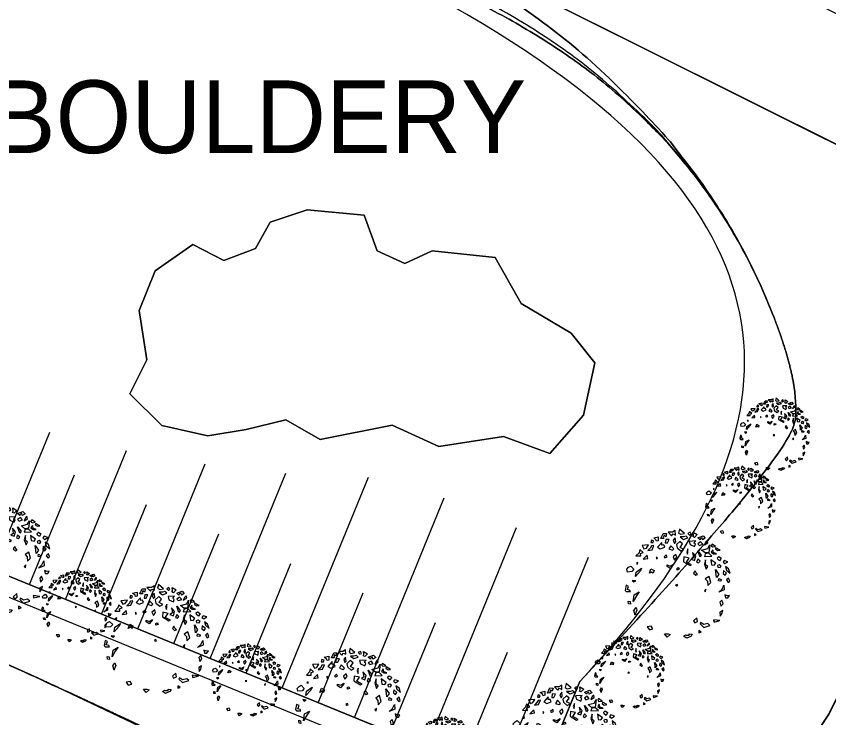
# Model space of a CAD drawing. Extents: x -504998 to -504814, y -1117353 to -1117234.
# Drawn here: x -504898.37 to -504887.95, y -1117325.65 to -1117316.66 of the extents above; entities that cross this region are included whole.
import ezdxf

# ---------------------------------------------------------------- set-up
doc = ezdxf.new("R2010")
doc.units = 0
for name, color, linetype in [('01_OPLOCENI', 7, 'Continuous'), ('01_ST tenká', 7, 'Continuous'), ('03_POPIS', 7, 'Continuous'), ('05_ZARIZ_PREDMETY', 7, 'Continuous'), ('10_ZIVE_PLOTY_KVETOUCI', 7, 'Continuous'), ('_01_CYKLOSTEZKA', 7, 'Continuous'), ('_01_pl', 7, 'Continuous'), ('_01_reka', 7, 'Continuous'), ('_01_ST tenká', 7, 'Continuous'), ('_01_svah', 7, 'Continuous'), ('_02_pl_ cesta', 7, 'Continuous'), ('Default', 7, 'Continuous'), ('res_uzemi', 7, 'Continuous')]:
    doc.layers.add(name, color=color, linetype=linetype)

# ---------------------------------------------------------------- blocks, each defined once
blk = doc.blocks.new('Deciduous Tree 1 PV_1')
at = {"layer": 'Default'}
for points in [[(-0.2248, 0.4729), (-0.2292, 0.4866), (-0.2556, 0.5084), (-0.207, 0.5208), (-0.2071, 0.4786)], [(-0.1783, 0.5014), (-0.1534, 0.5564), (-0.1189, 0.5548), (-0.128, 0.5216), (-0.1454, 0.5343), (-0.1535, 0.5142), (-0.1468, 0.5028)], [(-0.1029, 0.57), (-0.0664, 0.5317), (-0.0498, 0.553), (-0.0232, 0.5402), (-0.0265, 0.587), (-0.0564, 0.57)], [(0.021, 0.6025), (0.01, 0.5615), (0.0332, 0.5488), (0.073, 0.5573)], [(0.0265, 0.519), (0.063, 0.4935), (0.1095, 0.5105), (0.0896, 0.5275), (0.063, 0.519)], [(0.1327, 0.57), (0.1095, 0.5573), (0.1261, 0.5402), (0.1427, 0.5488)], [(0.1626, 0.5232), (0.1692, 0.536), (0.1659, 0.57), (0.209, 0.5445), (0.1792, 0.5147)], [(0.2157, 0.5105), (0.2721, 0.5317), (0.2953, 0.5062), (0.2655, 0.4892), (0.2621, 0.5105), (0.2422, 0.502), (0.2389, 0.4892)], [(-0.279, 0.4849), (-0.2864, 0.4595), (-0.2627, 0.4592), (-0.2569, 0.4769)], [(-0.1706, 0.461), (-0.2169, 0.4087), (-0.1858, 0.3917), (-0.1379, 0.4095), (-0.1489, 0.4345), (-0.1697, 0.4318)], [(-0.1271, 0.4925), (-0.1331, 0.4563), (-0.1094, 0.456), (-0.0926, 0.4909)], [(-0.0265, 0.5105), (-0.0465, 0.4849), (-0.0332, 0.4509), (-0.0199, 0.4679)], [(0.0232, 0.4722), (-0.0133, 0.4382), (-0.0066, 0.4041), (0.0332, 0.3701), (0.0664, 0.3871), (0.0265, 0.4084), (0.0531, 0.4467)], [(0.1925, 0.4764), (0.1228, 0.4722), (0.1327, 0.4382), (0.1792, 0.4169), (0.1891, 0.4424), (0.1725, 0.4552)], [(0.2455, 0.4679), (0.2157, 0.4467), (0.2323, 0.4296), (0.2688, 0.4424)], [(0.3152, 0.4807), (0.2986, 0.4637), (0.2854, 0.4339), (0.3219, 0.4552)], [(0.3683, 0.4424), (0.3584, 0.4254), (0.3716, 0.4126), (0.4048, 0.4169)], [(-0.4456, 0.3183), (-0.3927, 0.3171), (-0.396, 0.3438), (-0.3682, 0.3536), (-0.4037, 0.3843), (-0.4128, 0.3512)], [(-0.381, 0.4289), (-0.3598, 0.3921), (-0.3344, 0.3995), (-0.3122, 0.4336)], [(-0.318, 0.3737), (-0.2742, 0.3815), (-0.2533, 0.4264), (-0.2794, 0.4243), (-0.2922, 0.3995)], [(-0.073, 0.4254), (-0.0929, 0.3914), (-0.0564, 0.3786), (-0.0398, 0.3914)], [(0.1095, 0.3914), (0.0962, 0.3616), (0.1062, 0.3361), (0.1095, 0.3616)], [(0.1593, 0.3531), (0.1692, 0.2978), (0.1427, 0.2808), (0.1792, 0.268), (0.1925, 0.3148)], [(0.2389, 0.302), (0.2157, 0.3701), (0.2522, 0.3233)], [(0.2555, 0.3786), (0.3219, 0.3956), (0.3418, 0.4339), (0.3318, 0.3531), (0.292, 0.3488)], [(0.375, 0.3829), (0.3584, 0.3573), (0.3816, 0.3403), (0.4148, 0.3403), (0.3816, 0.3531)], [(0.4081, 0.4041), (0.4048, 0.3914), (0.428, 0.3743), (0.4546, 0.3786)], [(-0.3252, 0.3233), (-0.3683, 0.2808), (-0.3185, 0.2893)], [(-0.2256, 0.3063), (-0.2256, 0.285), (-0.2157, 0.2935)], [(-0.1228, 0.3276), (-0.146, 0.3063), (-0.136, 0.2978), (-0.1128, 0.3063)], [(-0.0199, 0.3318), (-0.0498, 0.3063), (-0.0332, 0.2723), (-0.01, 0.302)], [(0.0664, 0.3063), (0.063, 0.2552), (0.1327, 0.2127), (0.1493, 0.2212), (0.0929, 0.251), (0.1228, 0.2935)], [(0.2157, 0.2808), (0.2024, 0.251), (0.2223, 0.2425), (0.2389, 0.2595)], [(0.2953, 0.3403), (0.2854, 0.3105), (0.365, 0.3148), (0.3318, 0.3446)], [(0.2986, 0.2765), (0.2854, 0.2297), (0.3053, 0.1744), (0.3219, 0.2042), (0.2986, 0.2212)], [(0.355, 0.2765), (0.3617, 0.2212), (0.3915, 0.2169), (0.4081, 0.2382)], [(0.448, 0.2637), (0.428, 0.2808), (0.4247, 0.2978), (0.438, 0.3105), (0.4645, 0.2935)], [(0.4977, 0.268), (0.4845, 0.251), (0.5044, 0.234), (0.5375, 0.2552)], [(-0.5243, 0.1957), (-0.501, 0.2084), (-0.4679, 0.1744), (-0.4911, 0.1489), (-0.5375, 0.1446), (-0.5442, 0.1744)], [(-0.4513, 0.0978), (-0.4446, 0.1446), (-0.3849, 0.1872), (-0.3982, 0.1574)], [(-0.4247, 0.2467), (-0.4413, 0.234), (-0.428, 0.2297)], [(-0.302, 0.1319), (-0.2854, 0.1787), (-0.2522, 0.1616), (-0.2621, 0.1319), (-0.2787, 0.1446)], [(-0.0564, 0.2084), (-0.0796, 0.1829), (-0.1128, 0.2042), (-0.1128, 0.2212), (-0.0796, 0.2084), (-0.0431, 0.2297)], [(-0.0066, 0.1872), (0.0066, 0.1914), (0.0166, 0.1744), (-0.0066, 0.1659)], [(0.4645, 0.2084), (0.4446, 0.2212), (0.4247, 0.2127), (0.428, 0.1957), (0.4546, 0.1914)], [(0.511, 0.2042), (0.521, 0.1659), (0.5608, 0.1319), (0.5442, 0.1787)], [(0.1858, 0.1574), (0.1692, 0.1319), (0.1925, 0.1106), (0.2124, 0.1191), (0.1958, 0.1361)], [(0.2953, 0.0723), (0.3185, 0.0468), (0.3219, 0), (0.355, 0.034), (0.3351, 0.0978)], [(0.4048, 0.1702), (0.438, 0.1191), (0.4148, 0.0851), (0.4115, 0.1191)], [(0.4878, 0.1616), (0.4845, 0.1276), (0.5077, 0.1106), (0.521, 0.1319)], [(-0.5243, -0.0085), (-0.5508, 0.0043), (-0.5608, -0.051), (-0.5508, -0.0638), (-0.5044, -0.0638), (-0.511, -0.051), (-0.5375, -0.0425)], [(-0.4845, 0.0553), (-0.4679, 0.0383), (-0.448, 0.051)], [(-0.0066, 0.0128), (-0.0232, 0.0043), (-0.0133, -0.0043), (0, 0)], [(0.4645, 0.0638), (0.4612, 0.0468), (0.4347, 0.051), (0.438, 0.0766)], [(0.4944, 0.0043), (0.4977, -0.0468), (0.438, -0.0723), (0.4745, -0.0383)], [(0.521, 0.0596), (0.5409, 0.034), (0.5575, 0.0468), (0.5442, 0.0808)], [(-0.4745, -0.1702), (-0.4645, -0.0978), (-0.4115, -0.0681), (-0.4413, -0.1106)], [(0.302, -0.0383), (0.2854, -0.0553), (0.2986, -0.0681)], [(-0.5077, -0.1702), (-0.5044, -0.1999), (-0.5243, -0.1957), (-0.5276, -0.1659)], [(0.4712, -0.1574), (0.4513, -0.1787), (0.4612, -0.2212), (0.4845, -0.1957)], [(0.5044, -0.0978), (0.511, -0.1319), (0.5375, -0.1319), (0.5541, -0.1063), (0.5309, -0.1106)], [(-0.4546, -0.3148), (-0.4679, -0.268), (-0.4446, -0.234), (-0.4347, -0.2637), (-0.4446, -0.2808)], [(0.2057, -0.3446), (0.1692, -0.3786), (0.1825, -0.3999), (0.2124, -0.3829)], [(0.4811, -0.268), (0.4513, -0.285), (0.4546, -0.3276), (0.4712, -0.302)], [(-0.282, -0.4339), (-0.3252, -0.4424), (-0.302, -0.4722), (-0.2655, -0.4637)], [(0.2455, -0.3956), (0.2389, -0.4084), (0.2787, -0.4467), (0.3451, -0.4254), (0.3219, -0.4041), (0.2787, -0.4169)], [(0.3816, -0.3658), (0.3882, -0.3914), (0.4513, -0.3743)], [(-0.1128, -0.553), (-0.1394, -0.5147), (-0.1029, -0.5147), (-0.0796, -0.5232)], [(0.0962, -0.5615), (0.063, -0.5402), (0.083, -0.5275), (0.0896, -0.5317), (0.1228, -0.5317), (0.1228, -0.5147), (0.156, -0.519), (0.1427, -0.5402)], [(0.2256, -0.5062), (0.2522, -0.4977), (0.2256, -0.4807)]]:
    blk.add_lwpolyline(points, close=True, dxfattribs=at)

msp = doc.modelspace()

# ---------------------------------------------------------------- linework, layer by layer
at = {"layer": '01_OPLOCENI'}
msp.add_line((-504964.332, -1117297.166), (-504891.056, -1117327.134), dxfattribs=at)
at = {"layer": '01_ST tenká'}
for p in [(-504885.081, -1117319.864), (-504889.754, -1117328.346)]:
    msp.add_line(p, (-504887.95, -1117325.605), dxfattribs=at)
msp.add_lwpolyline([(-504895.908, -1117322.034), (-504896.498, -1117321.905), (-504896.908, -1117321.496), (-504896.693, -1117321.063), (-504896.792, -1117320.429), (-504896.584, -1117319.918), (-504896.1, -1117319.583), (-504895.704, -1117319.787), (-504895.3, -1117319.632), (-504895.11, -1117319.294), (-504894.635, -1117319.139), (-504893.907, -1117319.206), (-504893.74, -1117319.663), (-504893.386, -1117319.826), (-504893.035, -1117319.663), (-504892.225, -1117319.748), (-504891.893, -1117320.337), (-504891.254, -1117320.721), (-504890.951, -1117321.1), (-504891.094, -1117321.773), (-504891.524, -1117322.263), (-504892.121, -1117322.043), (-504892.95, -1117322.172), (-504893.545, -1117321.898), (-504894.47, -1117322.083), (-504894.908, -1117321.831), (-504895.417, -1117321.955)], close=True, dxfattribs=at)
msp.add_lwpolyline([(-504898.546, -1117322.158), (-504899.122, -1117323.565), (-504891.717, -1117326.594), (-504891.141, -1117325.186)], dxfattribs=at)
for points, degree in [([(-504979.676, -1117286.577), (-504975.526, -1117291.09), (-504971.924, -1117295.097), (-504967.609, -1117300.686), (-504961.055, -1117303.818), (-504949.588, -1117307.491), (-504933.661, -1117313.295), (-504916.676, -1117320.52), (-504900.945, -1117326.136), (-504889.034, -1117332.505), (-504883.929, -1117337.299), (-504881.859, -1117339.419)], 3), ([(-504980.257, -1117288.154), (-504977.765, -1117290.881), (-504976.785, -1117291.966), (-504974.842, -1117294.162), (-504973.881, -1117295.273), (-504972.466, -1117296.963), (-504971.765, -1117297.813), (-504971.076, -1117298.674), (-504970.619, -1117299.251), (-504970.394, -1117299.542), (-504969.896, -1117300.158), (-504969.627, -1117300.477), (-504969.169, -1117300.947), (-504969.007, -1117301.101), (-504968.678, -1117301.392), (-504968.51, -1117301.53), (-504967.657, -1117302.187), (-504966.932, -1117302.609), (-504965.846, -1117303.16), (-504965.484, -1117303.33), (-504964.768, -1117303.654), (-504964.416, -1117303.807), (-504963.358, -1117304.26), (-504962.653, -1117304.55), (-504959.129, -1117305.95), (-504956.315, -1117306.908), (-504952.123, -1117308.323), (-504950.732, -1117308.792), (-504947.95, -1117309.753), (-504943.777, -1117311.22), (-504939.618, -1117312.765), (-504934.102, -1117314.893), (-504931.361, -1117315.996), (-504925.877, -1117318.231), (-504923.135, -1117319.359), (-504918.999, -1117321.018), (-504917.616, -1117321.565), (-504914.845, -1117322.639), (-504913.46, -1117323.167), (-504909.316, -1117324.753), (-504906.566, -1117325.812), (-504902.501, -1117327.514), (-504901.156, -1117328.1), (-504898.491, -1117329.327), (-504897.173, -1117329.968), (-504894.596, -1117331.324), (-504893.337, -1117332.04), (-504890.908, -1117333.571), (-504889.742, -1117334.385), (-504887.004, -1117336.533), (-504885.468, -1117337.937), (-504883.972, -1117339.419)], 3), ([(-504888.655, -1117320.511), (-504890.285, -1117316.294), (-504903.106, -1117312.218), (-504898.546, -1117322.158)], 2), ([(-504891.141, -1117325.186), (-504888.47, -1117322.323), (-504888.306, -1117321.413), (-504888.655, -1117320.511)], 2)]:
    msp.add_open_spline(points, degree=degree, dxfattribs=at)
at = {"layer": '05_ZARIZ_PREDMETY'}
msp.add_lwpolyline([(-504895.417, -1117321.955), (-504894.908, -1117321.831), (-504894.47, -1117322.083), (-504893.545, -1117321.898), (-504892.95, -1117322.172), (-504892.121, -1117322.043), (-504891.524, -1117322.263), (-504891.094, -1117321.773), (-504890.951, -1117321.1), (-504891.254, -1117320.721), (-504891.254, -1117320.721), (-504891.893, -1117320.337), (-504892.225, -1117319.748), (-504892.225, -1117319.748), (-504893.035, -1117319.663), (-504893.386, -1117319.826), (-504893.74, -1117319.663), (-504893.907, -1117319.206), (-504893.907, -1117319.206), (-504894.635, -1117319.139), (-504895.11, -1117319.294), (-504895.3, -1117319.632), (-504895.704, -1117319.787), (-504896.1, -1117319.583), (-504896.584, -1117319.918), (-504896.792, -1117320.429), (-504896.693, -1117321.063), (-504896.908, -1117321.496), (-504896.498, -1117321.905), (-504895.908, -1117322.034)], close=True, dxfattribs=at)
at = {"layer": '10_ZIVE_PLOTY_KVETOUCI'}
msp.add_lwpolyline([(-504884.633, -1117320.087), (-504887.516, -1117325.855), (-504889.336, -1117328.621), (-504889.754, -1117328.346), (-504887.95, -1117325.605), (-504885.081, -1117319.864)], close=True, dxfattribs=at)
at = {"layer": '_01_CYKLOSTEZKA'}
msp.add_line((-504894.624, -1117314.913), (-504883.991, -1117320.228), dxfattribs=at)
for points in [[(-504978.999, -1117285.017), (-504976.7, -1117287.423), (-504974.687, -1117289.528), (-504972.137, -1117292.133), (-504971.625, -1117292.653), (-504970.597, -1117293.689), (-504970.083, -1117294.207), (-504969.05, -1117295.208), (-504968.53, -1117295.693), (-504967.466, -1117296.609), (-504966.923, -1117297.036), (-504964.081, -1117299.049), (-504961.455, -1117300.27), (-504956.072, -1117302.531), (-504953.347, -1117303.554), (-504945.119, -1117306.481), (-504939.563, -1117308.242), (-504928.573, -1117312.35), (-504923.185, -1117314.677), (-504915.108, -1117318.039), (-504912.41, -1117319.13), (-504907.001, -1117321.329), (-504904.293, -1117322.438), (-504900.239, -1117324.181), (-504898.887, -1117324.773), (-504896.196, -1117326.017), (-504894.86, -1117326.669), (-504892.238, -1117328.076), (-504890.953, -1117328.83), (-504888.469, -1117330.483), (-504887.279, -1117331.383), (-504883.84, -1117334.217), (-504881.711, -1117336.288), (-504879.247, -1117338.705), (-504878.883, -1117339.062), (-504878.518, -1117339.419)], [(-504979.438, -1117286.005), (-504976.794, -1117288.771), (-504973.013, -1117292.727), (-504966.78, -1117298.878), (-504954.231, -1117304.806), (-504936.613, -1117309.9), (-504917.359, -1117318.312), (-504902.231, -1117324.234), (-504889.176, -1117330.36), (-504883.067, -1117336.358), (-504879.947, -1117339.419)]]:
    msp.add_open_spline(points, degree=3, dxfattribs=at)
at = {"layer": '_01_pl'}
for points in [[(-504964.237, -1117296.934), (-504921.798, -1117314.291), (-504920.655, -1117311.495), (-504920.054, -1117311.795), (-504918.712, -1117309.112), (-504916.418, -1117310.259), (-504916.418, -1117310.259), (-504915.076, -1117310.93), (-504915.076, -1117310.93), (-504914.538, -1117311.2), (-504910.338, -1117302.802), (-504910.336, -1117302.802), (-504912.038, -1117306.206), (-504913.379, -1117308.889), (-504906.224, -1117312.467), (-504898.929, -1117316.112), (-504897.587, -1117313.429), (-504894.624, -1117314.913), (-504883.991, -1117320.228)], [(-504883.991, -1117320.228), (-504894.624, -1117314.913), (-504893.953, -1117313.571), (-504883.045, -1117319.024)], [(-504891.141, -1117325.186), (-504891.717, -1117326.594), (-504899.122, -1117323.565), (-504898.546, -1117322.158)], [(-504898.546, -1117322.158), (-504899.122, -1117323.565), (-504891.717, -1117326.594), (-504891.141, -1117325.186)], [(-504898.095, -1117325.141), (-504899.494, -1117324.513), (-504900.964, -1117323.87)]]:
    msp.add_lwpolyline(points, dxfattribs=at)
for points in [[(-504895.908, -1117322.034), (-504896.498, -1117321.905), (-504896.908, -1117321.496), (-504896.693, -1117321.063), (-504896.792, -1117320.429), (-504896.584, -1117319.918), (-504896.1, -1117319.583), (-504895.704, -1117319.787), (-504895.3, -1117319.632), (-504895.11, -1117319.294), (-504894.635, -1117319.139), (-504893.907, -1117319.206), (-504893.74, -1117319.663), (-504893.386, -1117319.826), (-504893.035, -1117319.663), (-504892.225, -1117319.748), (-504891.893, -1117320.337), (-504891.254, -1117320.721), (-504890.951, -1117321.1), (-504891.094, -1117321.773), (-504891.524, -1117322.263), (-504892.121, -1117322.043), (-504892.95, -1117322.172), (-504893.545, -1117321.898), (-504894.47, -1117322.083), (-504894.908, -1117321.831), (-504895.417, -1117321.955)], [(-504895.417, -1117321.955), (-504894.908, -1117321.831), (-504894.47, -1117322.083), (-504893.545, -1117321.898), (-504892.95, -1117322.172), (-504892.121, -1117322.043), (-504891.524, -1117322.263), (-504891.094, -1117321.773), (-504890.951, -1117321.1), (-504891.254, -1117320.721), (-504891.893, -1117320.337), (-504892.225, -1117319.748), (-504893.035, -1117319.663), (-504893.386, -1117319.826), (-504893.74, -1117319.663), (-504893.907, -1117319.206), (-504894.635, -1117319.139), (-504895.11, -1117319.294), (-504895.3, -1117319.632), (-504895.704, -1117319.787), (-504896.1, -1117319.583), (-504896.584, -1117319.918), (-504896.792, -1117320.429), (-504896.693, -1117321.063), (-504896.908, -1117321.496), (-504896.498, -1117321.905), (-504895.908, -1117322.034)], [(-504889.754, -1117328.346), (-504889.336, -1117328.621), (-504887.516, -1117325.855), (-504884.633, -1117320.087), (-504885.081, -1117319.864), (-504887.95, -1117325.605)]]:
    msp.add_lwpolyline(points, close=True, dxfattribs=at)
for points in [[(-504898.546, -1117322.158), (-504903.106, -1117312.218), (-504890.285, -1117316.294), (-504888.655, -1117320.511)], [(-504888.655, -1117320.511), (-504889.823, -1117317.489), (-504896.736, -1117314.54), (-504898.885, -1117316.768)], [(-504888.655, -1117320.511), (-504889.735, -1117317.717), (-504895.727, -1117314.985), (-504898.323, -1117316.35)], [(-504898.323, -1117316.35), (-504895.727, -1117314.985), (-504889.735, -1117317.717), (-504888.655, -1117320.511)], [(-504888.655, -1117320.511), (-504888.306, -1117321.413), (-504888.47, -1117322.323), (-504891.141, -1117325.186)], [(-504891.141, -1117325.186), (-504888.47, -1117322.323), (-504888.306, -1117321.413), (-504888.655, -1117320.511)], [(-504897.541, -1117325.395), (-504897.726, -1117325.31), (-504897.91, -1117325.225), (-504898.095, -1117325.141)], [(-504897.057, -1117325.621), (-504897.218, -1117325.545), (-504897.38, -1117325.47), (-504897.541, -1117325.395)], [(-504896.784, -1117325.749), (-504896.875, -1117325.706), (-504896.966, -1117325.663), (-504897.057, -1117325.621)]]:
    msp.add_open_spline(points, degree=2, dxfattribs=at)
at = {"layer": '_01_reka'}
for points in [[(-504888.436, -1117333.516), (-504891.673, -1117331.094), (-504900.945, -1117326.136), (-504916.676, -1117320.52), (-504933.661, -1117313.295), (-504949.588, -1117307.491), (-504961.055, -1117303.818), (-504967.609, -1117300.686), (-504971.924, -1117295.097), (-504975.526, -1117291.09), (-504979.676, -1117286.577)], [(-504980.257, -1117288.154), (-504977.765, -1117290.881), (-504976.785, -1117291.966), (-504974.842, -1117294.162), (-504973.881, -1117295.273), (-504972.466, -1117296.963), (-504971.765, -1117297.813), (-504971.076, -1117298.674), (-504970.619, -1117299.251), (-504970.394, -1117299.542), (-504969.896, -1117300.158), (-504969.627, -1117300.477), (-504969.169, -1117300.947), (-504969.007, -1117301.101), (-504968.678, -1117301.392), (-504968.51, -1117301.53), (-504967.657, -1117302.187), (-504966.932, -1117302.609), (-504965.846, -1117303.16), (-504965.484, -1117303.33), (-504964.768, -1117303.654), (-504964.416, -1117303.807), (-504963.358, -1117304.26), (-504962.653, -1117304.55), (-504959.129, -1117305.95), (-504956.315, -1117306.908), (-504952.123, -1117308.323), (-504950.732, -1117308.792), (-504947.95, -1117309.753), (-504943.777, -1117311.22), (-504939.618, -1117312.765), (-504934.102, -1117314.893), (-504931.361, -1117315.996), (-504925.877, -1117318.231), (-504923.135, -1117319.359), (-504918.999, -1117321.018), (-504917.616, -1117321.565), (-504914.845, -1117322.639), (-504913.46, -1117323.167), (-504909.316, -1117324.753), (-504906.566, -1117325.812), (-504902.501, -1117327.514), (-504901.156, -1117328.1), (-504898.491, -1117329.327), (-504897.173, -1117329.968), (-504894.596, -1117331.324), (-504893.337, -1117332.04), (-504890.908, -1117333.571), (-504889.742, -1117334.385), (-504888.623, -1117335.262)]]:
    msp.add_open_spline(points, degree=3, dxfattribs=at)
at = {"layer": '_01_ST tenká'}
msp.add_open_spline([(-504891.141, -1117325.186), (-504888.47, -1117322.323), (-504887.541, -1117317.166), (-504903.106, -1117312.218), (-504898.546, -1117322.158)], degree=3, dxfattribs=at)
at = {"layer": '_01_svah'}
for p, q in [((-504891.717, -1117326.594), (-504911.935, -1117318.325)), ((-504898.659, -1117323.755), (-504897.936, -1117321.987)), ((-504897.733, -1117324.133), (-504896.951, -1117322.222)), ((-504896.808, -1117324.512), (-504895.943, -1117322.397)), ((-504898.196, -1117323.944), (-504897.621, -1117322.537)), ((-504895.882, -1117324.89), (-504894.91, -1117322.514)), ((-504894.957, -1117325.269), (-504893.852, -1117322.567)), ((-504894.031, -1117325.647), (-504892.88, -1117322.833)), ((-504897.271, -1117324.322), (-504896.695, -1117322.915)), ((-504893.105, -1117326.026), (-504891.954, -1117323.211)), ((-504896.345, -1117324.701), (-504895.769, -1117323.294)), ((-504895.419, -1117325.08), (-504894.844, -1117323.672)), ((-504892.18, -1117326.404), (-504891.029, -1117323.59)), ((-504894.494, -1117325.458), (-504893.918, -1117324.051)), ((-504893.568, -1117325.837), (-504892.993, -1117324.429)), ((-504892.643, -1117326.215), (-504892.067, -1117324.808)), ((-504891.717, -1117326.594), (-504891.141, -1117325.186))]:
    msp.add_line(p, q, dxfattribs=at)
at = {"layer": '_02_pl_ cesta'}
for points in [[(-504879.612, -1117338.347), (-504881.711, -1117336.288), (-504883.84, -1117334.217), (-504887.279, -1117331.383), (-504888.469, -1117330.483), (-504890.953, -1117328.83), (-504892.238, -1117328.076), (-504894.86, -1117326.669), (-504896.196, -1117326.017), (-504898.887, -1117324.773), (-504900.239, -1117324.181), (-504904.293, -1117322.438), (-504907.001, -1117321.329), (-504912.41, -1117319.13), (-504915.108, -1117318.039), (-504923.185, -1117314.677), (-504928.573, -1117312.35), (-504939.563, -1117308.242), (-504945.119, -1117306.481), (-504953.347, -1117303.554), (-504956.072, -1117302.531), (-504961.455, -1117300.27), (-504964.081, -1117299.049), (-504966.923, -1117297.036), (-504967.466, -1117296.609), (-504968.53, -1117295.693), (-504969.05, -1117295.208), (-504970.083, -1117294.207), (-504970.597, -1117293.689), (-504971.625, -1117292.653), (-504972.137, -1117292.133), (-504974.687, -1117289.528), (-504976.7, -1117287.423), (-504978.999, -1117285.017)], [(-504979.438, -1117286.005), (-504976.794, -1117288.771), (-504973.013, -1117292.727), (-504966.78, -1117298.878), (-504954.231, -1117304.806), (-504936.613, -1117309.9), (-504917.359, -1117318.312), (-504902.231, -1117324.234), (-504893.156, -1117328.493), (-504889.765, -1117330.828)]]:
    msp.add_open_spline(points, degree=3, dxfattribs=at)
at = {"layer": 'res_uzemi'}
msp.add_lwpolyline([(-504895.316, -1117326.46), (-504898.095, -1117325.141), (-504899.494, -1117324.513), (-504900.964, -1117323.87), (-504903.929, -1117322.607), (-504906.832, -1117321.402), (-504910.082, -1117320.076), (-504912.108, -1117319.253), (-504914.011, -1117318.478), (-504919.244, -1117316.315), (-504925.453, -1117313.719), (-504927.742, -1117312.778), (-504931.511, -1117311.273), (-504936.157, -1117309.529), (-504942.139, -1117307.443)], dxfattribs=at)

# ---------------------------------------------------------------- block references
at = {"layer": '10_ZIVE_PLOTY_KVETOUCI'}
for p, xscale, yscale in [((-504888.643, -1117322.031), 0.8, 0.8000000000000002), ((-504889.081, -1117322.907), 0.8, 0.8000000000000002), ((-504898.607, -1117323.645), 1.2000000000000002, 1.2000000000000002), ((-504889.887, -1117323.956), 1.2000000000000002, 1.2000000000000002), ((-504897.593, -1117324.235), 0.8, 0.8000000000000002), ((-504896.567, -1117324.665), 1.2000000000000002, 1.2000000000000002), ((-504890.506, -1117325.077), 0.8, 0.8000000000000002), ((-504895.412, -1117325.182), 0.8, 0.8000000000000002), ((-504894.112, -1117325.485), 1.2000000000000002, 1.2000000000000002), ((-504891.342, -1117325.937), 1.2000000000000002, 1.2000000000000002), ((-504892.883, -1117326.113), 0.8, 0.8000000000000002)]:
    msp.add_blockref('Deciduous Tree 1 PV_1', p, dxfattribs=dict(at, xscale=xscale, yscale=yscale))

# ---------------------------------------------------------------- texts
at = {"layer": '03_POPIS'}
msp.add_text('BOULDERY', height=0.9331, dxfattribs=at).set_placement((-504898.694, -1117318.411))

doc.saveas('drawing.dxf')
